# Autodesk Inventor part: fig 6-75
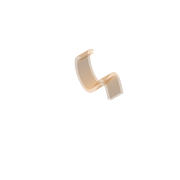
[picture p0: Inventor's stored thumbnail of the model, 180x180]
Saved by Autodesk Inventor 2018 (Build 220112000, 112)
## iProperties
Shininess: 64.0
Length Units: 11269
Angle Units: 11279
Time Units: 11290
Mass Units: 11283
Length Display Precision: 3
Angle Display Precision: 2
Compacted: True
Part Number: fig 6-75
Document SubType Name: Modeling
Created: 2002-12
Designer: deepak
Density: 1 g/cm^3
Material: Generic
Appearance: Default
Density: 0.0
Volumn: 0.0
Area: 0.0
PropertySet Name: Model Information
Control State: 0
Master: False
Checked Out: False
Author: deepak
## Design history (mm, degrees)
sketch "Sketch1"
  geometry: 5 further points
  constraints: 5 other
extrude_surface "ExtrusionSrf1" sketch "Sketch1" dims "d0" = 20, "d1" = 0
feature "OffsetSrf2" dims "d8" = 4, "d9" = 4
body "Solid1"
body "Srf1"
body "Srf2"
